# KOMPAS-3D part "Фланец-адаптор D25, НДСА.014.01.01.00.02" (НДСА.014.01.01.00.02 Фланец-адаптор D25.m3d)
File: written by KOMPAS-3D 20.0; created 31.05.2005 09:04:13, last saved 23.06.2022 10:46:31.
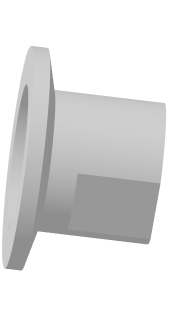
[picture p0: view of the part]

Document properties: Полное имя файла: C:\Users\cherbakova\Desktop\PLM\НДСА.014.01.01.00.02 Фланец-адаптор D25.m3d

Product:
- Part/product: Фланец-адаптор D25  | designation НДСА.014.01.01.00.02
    Материал: Сталь 12Х18Н10Т ГОСТ 5632-72 (density 7900 kg/m3)
    Масса: 0.0774996
    additional columns: <item xmlns="http://appius.ru/pdm" xmlns:xs="http://www.w3.org/2001/XMLSchema" x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; <item xmlns="http://appius.ru/pdm" xmlns:xs="http://www.w3.org/2001/XMLSchema" x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; <item xmlns="http://appius.ru/pdm" xmlns:xs="http://www.w3.org/2001/XMLSchema" x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; <item xmlns="http://appius.ru/pdm" xmlns:xs="http://www.w3.org/2001/XMLSchema" x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; <item xmlns="http://appius.ru/pdm" xmlns:xs="http://www.w3.org/2001/XMLSchema" x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; <item xmlns="http://appius.ru/pdm" xmlns:xs="http://www.w3.org/2001/XMLSchema" x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
    source file: НДСА.014.01.01.00.02 Фланец-адаптор D25.CDW

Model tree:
1. Плоскость XY
2. Плоскость ZX
3. Плоскость ZY
4. Начало координат
5. Эскиз:1
6. Операция вращения:1
     Угол 1 = 360
7. Условное изображение резьбы:1  (labels: Операция вращения:1; Операция вращения:1)
     Длина резьбы = 10; Шаг резьбы = 1.8; Номинальный диаметр резьбы = 16.662
8. Фаска:1  (labels: Операция вращения:1)
     Угол = 45; Длина 1 = 1; Длина 2 = 1
9. Эскиз:2  (labels: Операция вращения:1)
10. Вырезать элемент выдавливания:1  (labels: Сталь 12Х18Н10Т ГОСТ 5632-72)
     Расстояние 1 = 15

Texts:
  НДСА.014.01.01.00.02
